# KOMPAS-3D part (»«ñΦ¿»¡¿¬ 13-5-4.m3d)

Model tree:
1. Эскиз:5
2. Операция вращения:2
     Угол 1 = 360
3. Эскиз:6
4. Операция выдавливания:3
     Расстояние 1 = 4; Расстояние 2 = 4
5. Эскиз:8
6. Отверстие:3
7. Эскиз:9
8. Операция выдавливания:4
     Расстояние 1 = 4; Расстояние 2 = 4
9. Эскиз:10
10. Отверстие:4
11. Эскиз:11
12. Операция вращения:3
     Угол 1 = 360
13. Массив по концентрической сетке:2  (with: Операция вращения:3)  (labels: Экземпляр ( 1, 1 ); Экземпляр ( 1, 2 ); Экземпляр ( 1, 3 ); Экземпляр ( 1, 4 ))
     N 2 = 10; Шаг 2 = 360
14. Скругление:1
     Радиус = 0.1

Referenced files in C:\Program Files\ASCON\KOMPAS-3D V12\Sys\: holelib.lfr
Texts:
  подшипник 13
  подшипник 13х5х4
  Отверстие 01
  (вариант 1)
